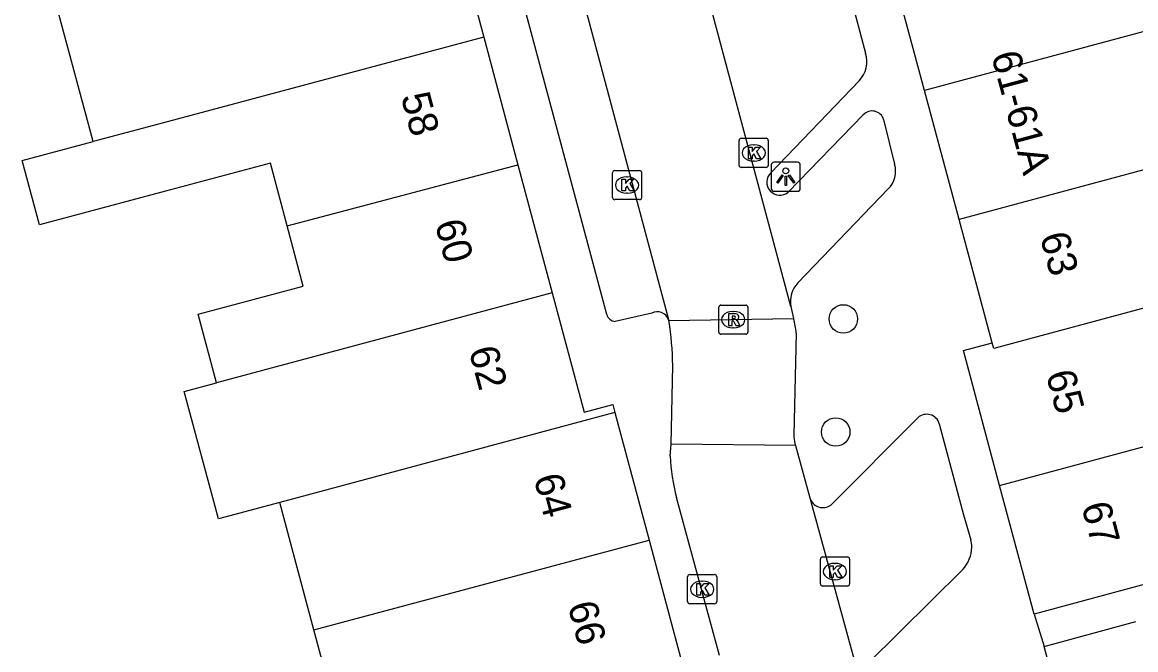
# Model space of a CAD drawing. Extents: x 162542 to 163144, y 380786 to 381511.
# Drawn here: x 162823.08 to 162861.28, y 380893 to 380914.51 of the extents above; entities that cross this region are included whole.
import ezdxf

# ---------------------------------------------------------------- set-up
doc = ezdxf.new("R2010")
doc.units = 0
for name, color, linetype in [('IMGEO_Boom', 7, 'Continuous'), ('IMGEO_Kolk', 7, 'Continuous'), ('IMGEO_Lichtpunt', 7, 'Continuous'), ('IMGEO_Pand', 7, 'Continuous'), ('IMGEO_Pand_nummerreeks', 7, 'Continuous'), ('IMGEO_Rijbaan_lokaal_open', 7, 'Continuous'), ('IMGEO_Rioolput', 7, 'Continuous'), ('IMGEO_Voetpad_open', 7, 'Continuous')]:
    doc.layers.add(name, color=color, linetype=linetype)

msp = doc.modelspace()

# ---------------------------------------------------------------- linework, layer by layer
at = {"layer": 'IMGEO_Boom'}
for centre in [(162851.249, 380904.339), (162850.989, 380900.462)]:
    msp.add_circle(centre, 0.489, dxfattribs=at)
at = {"layer": 'IMGEO_Kolk'}
for p, q in [((162847.674, 380909.606), (162847.674, 380910.458)), ((162847.749, 380910.532), (162848.601, 380910.532)), ((162848.162, 380910.312), (162848.187, 380910.312)), ((162848.675, 380910.458), (162848.675, 380909.606)), ((162848.185, 380909.752), (162848.16, 380909.752)), ((162843.329, 380908.503), (162843.329, 380909.355)), ((162843.404, 380909.429), (162844.256, 380909.429)), ((162843.817, 380909.209), (162843.842, 380909.209)), ((162844.33, 380909.355), (162844.33, 380908.503)), ((162848.601, 380909.532), (162847.749, 380909.532)), ((162844.256, 380908.429), (162843.404, 380908.429)), ((162843.84, 380908.649), (162843.815, 380908.649)), ((162850.536, 380896.179), (162851.388, 380896.179)), ((162850.461, 380895.253), (162850.461, 380896.105)), ((162850.949, 380895.959), (162850.974, 380895.959)), ((162851.462, 380896.105), (162851.462, 380895.253)), ((162845.906, 380894.646), (162845.906, 380895.498)), ((162845.981, 380895.572), (162846.833, 380895.572)), ((162846.907, 380895.498), (162846.907, 380894.646)), ((162846.394, 380895.352), (162846.419, 380895.352)), ((162851.388, 380895.179), (162850.536, 380895.179)), ((162850.972, 380895.399), (162850.947, 380895.399)), ((162846.417, 380894.792), (162846.392, 380894.792)), ((162846.833, 380894.572), (162845.981, 380894.572))]:
    msp.add_line(p, q, dxfattribs=at)
for points in [[(162847.674, 380909.606), (162847.674, 380910.458)], [(162847.749, 380910.532), (162848.601, 380910.532)], [(162848.675, 380910.458), (162848.675, 380909.606)], [(162847.995, 380910.232), (162848.118, 380910.232), (162848.118, 380910.081), (162848.248, 380910.232), (162848.412, 380910.232), (162848.266, 380910.081), (162848.419, 380909.832), (162848.267, 380909.832), (162848.182, 380909.996), (162848.118, 380909.929), (162848.118, 380909.832), (162847.995, 380909.832), (162847.995, 380910.232)], [(162843.329, 380908.503), (162843.329, 380909.355)], [(162843.404, 380909.429), (162844.256, 380909.429)], [(162844.33, 380909.355), (162844.33, 380908.503)], [(162848.601, 380909.532), (162847.749, 380909.532)], [(162843.65, 380909.129), (162843.773, 380909.129), (162843.773, 380908.978), (162843.903, 380909.129), (162844.067, 380909.129), (162843.921, 380908.978), (162844.074, 380908.729), (162843.922, 380908.729), (162843.837, 380908.893), (162843.773, 380908.826), (162843.773, 380908.729), (162843.65, 380908.729), (162843.65, 380909.129)], [(162844.256, 380908.429), (162843.404, 380908.429)], [(162850.536, 380896.179), (162851.388, 380896.179)], [(162850.461, 380895.253), (162850.461, 380896.105)], [(162850.782, 380895.879), (162850.905, 380895.879), (162850.905, 380895.728), (162851.035, 380895.879), (162851.199, 380895.879), (162851.053, 380895.728), (162851.206, 380895.479), (162851.054, 380895.479), (162850.969, 380895.643), (162850.905, 380895.576), (162850.905, 380895.479), (162850.782, 380895.479), (162850.782, 380895.879)], [(162851.462, 380896.105), (162851.462, 380895.253)], [(162845.906, 380894.646), (162845.906, 380895.498)], [(162845.981, 380895.572), (162846.833, 380895.572)], [(162846.907, 380895.498), (162846.907, 380894.646)], [(162846.227, 380895.272), (162846.35, 380895.272), (162846.35, 380895.121), (162846.48, 380895.272), (162846.644, 380895.272), (162846.498, 380895.121), (162846.651, 380894.872), (162846.499, 380894.872), (162846.414, 380895.036), (162846.35, 380894.969), (162846.35, 380894.872), (162846.227, 380894.872), (162846.227, 380895.272)], [(162851.388, 380895.179), (162850.536, 380895.179)], [(162846.833, 380894.572), (162845.981, 380894.572)]]:
    msp.add_lwpolyline(points, dxfattribs=at)
for centre, start, end in [((162847.751, 380910.456), 91.552, 178.448), ((162847.751, 380910.456), 91.552, 178.448), ((162848.599, 380910.456), 1.552, 88.448), ((162848.599, 380910.456), 1.552, 88.448), ((162847.751, 380909.608), 181.552, 268.448), ((162847.751, 380909.608), 181.552, 268.448), ((162848.599, 380909.608), 271.552, 358.448), ((162848.599, 380909.608), 271.552, 358.448), ((162843.406, 380909.353), 91.552, 178.448), ((162843.406, 380909.353), 91.552, 178.448), ((162844.254, 380909.353), 1.552, 88.448), ((162844.254, 380909.353), 1.552, 88.448), ((162843.406, 380908.505), 181.552, 268.448), ((162843.406, 380908.505), 181.552, 268.448), ((162844.254, 380908.505), 271.552, 358.448), ((162844.254, 380908.505), 271.552, 358.448), ((162850.538, 380896.103), 91.552, 178.448), ((162850.538, 380896.103), 91.552, 178.448), ((162851.386, 380896.103), 1.552, 88.448), ((162851.386, 380896.103), 1.552, 88.448), ((162845.983, 380895.496), 91.552, 178.448), ((162845.983, 380895.496), 91.552, 178.448), ((162846.831, 380895.496), 1.552, 88.448), ((162846.831, 380895.496), 1.552, 88.448), ((162850.538, 380895.255), 181.552, 268.448), ((162850.538, 380895.255), 181.552, 268.448), ((162851.386, 380895.255), 271.552, 358.448), ((162851.386, 380895.255), 271.552, 358.448), ((162845.983, 380894.648), 181.552, 268.448), ((162845.983, 380894.648), 181.552, 268.448), ((162846.831, 380894.648), 271.552, 358.448), ((162846.831, 380894.648), 271.552, 358.448)]:
    msp.add_arc(centre, 0.0765, start, end, dxfattribs=at)
for centre, major_axis, ratio, start_param, end_param in [((162848.161, 380910.032), (-0.387, 0.002), 0.722429, 4.712389, 7.853982), ((162848.186, 380910.032), (-0.39, 0.002), 0.717154, 1.570796, 4.712389), ((162843.816, 380908.929), (-0.387, 0.002), 0.722429, 4.712389, 7.853982), ((162843.841, 380908.929), (-0.39, 0.002), 0.717154, 1.570796, 4.712389), ((162850.948, 380895.679), (-0.387, 0.002), 0.722429, 4.712389, 7.853982), ((162850.973, 380895.679), (-0.39, 0.002), 0.717154, 1.570796, 4.712389), ((162846.393, 380895.072), (-0.387, 0.002), 0.722429, 4.712389, 7.853982), ((162846.418, 380895.072), (-0.39, 0.002), 0.717154, 1.570796, 4.712389)]:
    msp.add_ellipse(centre, major_axis=major_axis, ratio=ratio, start_param=start_param, end_param=end_param, dxfattribs=at)
at = {"layer": 'IMGEO_Lichtpunt'}
for p, q in [((162848.776, 380909.618), (162848.776, 380908.811)), ((162848.776, 380909.618), (162848.776, 380908.811)), ((162849.678, 380909.713), (162848.87, 380909.713)), ((162849.678, 380909.713), (162848.87, 380909.713)), ((162849.772, 380908.811), (162849.772, 380909.618)), ((162849.772, 380908.811), (162849.772, 380909.618)), ((162848.87, 380908.717), (162849.678, 380908.717)), ((162848.87, 380908.717), (162849.678, 380908.717))]:
    msp.add_line(p, q, dxfattribs=at)
for points in [[(162849.15, 380909.282), (162849.189, 380909.254), (162849.001, 380908.992), (162848.963, 380909.019), (162849.15, 380909.282)], [(162849.252, 380909.234), (162849.299, 380909.234), (162849.299, 380908.912), (162849.252, 380908.912), (162849.252, 380909.234)], [(162849.362, 380909.254), (162849.4, 380909.281), (162849.587, 380909.019), (162849.548, 380908.991), (162849.362, 380909.254)]]:
    msp.add_lwpolyline(points, dxfattribs=at)
msp.add_circle((162849.275, 380909.416), 0.0994, dxfattribs=at)
for centre, start, end in [((162848.87, 380909.618), 90, 180), ((162848.87, 380909.618), 90, 180), ((162849.678, 380909.618), 0, 90), ((162849.678, 380909.618), 0, 90), ((162848.87, 380908.811), 180, 270), ((162848.87, 380908.811), 180, 270), ((162849.678, 380908.811), 270, 0), ((162849.678, 380908.811), 270, 360)]:
    msp.add_arc(centre, 0.0946, start, end, dxfattribs=at)
at = {"layer": 'IMGEO_Pand'}
for points in [[(162837.741, 380918.379), (162838.912, 380914.003)], [(162854.034, 380912.167), (162852.845, 380916.589)], [(162825.505, 380910.42), (162824.335, 380914.784)], [(162862.161, 380914.352), (162854.034, 380912.167)], [(162838.912, 380914.003), (162827.404, 380910.928), (162825.505, 380910.42)], [(162838.912, 380914.003), (162840.083, 380909.627)], [(162855.223, 380907.745), (162854.034, 380912.167)], [(162866.707, 380910.832), (162855.223, 380907.745)], [(162832.165, 380907.529), (162831.59, 380909.682), (162827.994, 380908.721), (162823.668, 380907.565), (162823.078, 380909.771), (162825.505, 380910.42)], [(162832.165, 380907.529), (162840.083, 380909.627)], [(162840.083, 380909.627), (162841.258, 380905.238)], [(162856.358, 380903.525), (162855.223, 380907.745)], [(162829.742, 380902.151), (162829.113, 380904.502), (162832.717, 380905.466), (162832.165, 380907.529)], [(162841.258, 380905.238), (162829.742, 380902.151)], [(162841.258, 380905.238), (162842.355, 380901.14), (162843.341, 380901.403), (162843.414, 380901.131)], [(162863.302, 380905.175), (162856.414, 380903.323), (162856.358, 380903.525)], [(162856.611, 380898.634), (162855.367, 380903.258), (162856.358, 380903.525)], [(162831.918, 380898.048), (162829.81, 380897.482), (162828.637, 380901.855), (162829.742, 380902.151)], [(162856.611, 380898.634), (162868.063, 380901.714)], [(162843.414, 380901.131), (162836.687, 380899.327), (162835.449, 380898.995), (162834.559, 380898.756), (162831.918, 380898.048)], [(162843.414, 380901.131), (162844.582, 380896.759)], [(162857.799, 380894.216), (162856.611, 380898.634)], [(162833.086, 380893.676), (162832.421, 380896.165), (162831.918, 380898.048)], [(162869.251, 380897.297), (162865.74, 380896.352), (162862.628, 380895.515), (162857.799, 380894.216)], [(162833.086, 380893.676), (162844.582, 380896.759)], [(162844.582, 380896.759), (162845.752, 380892.384)], [(162834.249, 380889.327), (162833.628, 380891.65), (162833.086, 380893.676)]]:
    msp.add_lwpolyline(points, dxfattribs=at)
at = {"layer": 'IMGEO_Rijbaan_lokaal_open'}
for points in [[(162833.101, 380949.771), (162845.249, 380904.323)], [(162849.452, 380904.763), (162838.69, 380945.047)], [(162849.452, 380904.763), (162849.544, 380904.353)], [(162845.265, 380904.285), (162845.249, 380904.323)], [(162845.265, 380904.285), (162849.544, 380904.353)], [(162849.634, 380903.856), (162849.549, 380900.368)], [(162845.34, 380900.044), (162845.396, 380902.748)], [(162845.309, 380899.648), (162845.34, 380900.044)], [(162849.608, 380900.004), (162845.34, 380900.044)], [(162849.59, 380900.072), (162849.608, 380900.004)], [(162849.608, 380900.004), (162850.098, 380898.2)], [(162847.005, 380892.801), (162845.528, 380898.214)], [(162850.098, 380898.2), (162851.913, 380891.569)]]:
    msp.add_lwpolyline(points, dxfattribs=at)
for centre, radius, start, end in [((162834.894, 380902.627), 10.503, 0.6601, 9.0831), ((162845.949, 380903.445), 3.708, 6.3585, 14.17), ((162850.83, 380900.395), 1.282, 181.191, 194.5811), ((162852.255, 380899.975), 6.953, 182.6956, 194.6706)]:
    msp.add_arc(centre, radius, start, end, dxfattribs=at)
at = {"layer": 'IMGEO_Rioolput'}
for p, q in [((162846.973, 380903.889), (162846.973, 380904.741)), ((162847.048, 380904.815), (162847.9, 380904.815)), ((162847.461, 380904.595), (162847.486, 380904.595)), ((162847.974, 380904.741), (162847.974, 380903.889)), ((162847.9, 380903.815), (162847.048, 380903.815)), ((162847.484, 380904.035), (162847.459, 380904.035))]:
    msp.add_line(p, q, dxfattribs=at)
for points in [[(162846.973, 380903.889), (162846.973, 380904.741)], [(162847.048, 380904.815), (162847.9, 380904.815)], [(162847.974, 380904.741), (162847.974, 380903.889)], [(162847.562, 380904.513), (162847.31, 380904.515), (162847.31, 380904.115)], [(162847.31, 380904.115), (162847.434, 380904.115), (162847.434, 380904.277), (162847.445, 380904.277)], [(162847.488, 380904.434), (162847.434, 380904.434), (162847.434, 380904.353)], [(162847.434, 380904.353), (162847.486, 380904.353)], [(162847.492, 380904.248), (162847.563, 380904.115), (162847.703, 380904.115), (162847.638, 380904.241)], [(162847.9, 380903.815), (162847.048, 380903.815)]]:
    msp.add_lwpolyline(points, dxfattribs=at)
for centre, radius, start, end in [((162847.05, 380904.739), 0.0765, 91.552, 178.448), ((162847.05, 380904.739), 0.0765, 91.552, 178.448), ((162847.898, 380904.739), 0.0765, 1.552, 88.448), ((162847.898, 380904.739), 0.0765, 1.552, 88.448), ((162847.444, 380904.224), 0.0533, 26.0293, 88.6989), ((162847.47, 380904.542), 0.19, 274.7715, 282.9687), ((162847.494, 380904.338), 0.0964, 77.0061, 93.1865), ((162847.508, 380904.395), 0.0378, 276.6634, 79.6772), ((162847.561, 380904.403), 0.109, 350.3612, 89.416), ((162847.559, 380904.403), 0.112, 277.5842, 350.9817), ((162847.543, 380904.188), 0.108, 29.5134, 73.7905), ((162847.05, 380903.891), 0.0765, 181.552, 268.448), ((162847.05, 380903.891), 0.0765, 181.552, 268.448), ((162847.898, 380903.891), 0.0765, 271.552, 358.448), ((162847.898, 380903.891), 0.0765, 271.552, 358.448)]:
    msp.add_arc(centre, radius, start, end, dxfattribs=at)
for centre, major_axis, ratio, start_param, end_param in [((162847.46, 380904.315), (-0.387, 0.002), 0.722429, 4.712389, 7.853982), ((162847.485, 380904.315), (-0.39, 0.002), 0.717154, 1.570796, 4.712389)]:
    msp.add_ellipse(centre, major_axis=major_axis, ratio=ratio, start_param=start_param, end_param=end_param, dxfattribs=at)
at = {"layer": 'IMGEO_Voetpad_open'}
for points in [[(162843.131, 380904.495), (162831.307, 380948.599)], [(162846.658, 380933.566), (162852.015, 380913.45)], [(162851.793, 380912.507), (162848.757, 380909.349)], [(162849.355, 380908.684), (162851.934, 380911.339)], [(162852.631, 380911.18), (162853.009, 380909.647)], [(162852.789, 380908.797), (162849.683, 380905.576)], [(162844.684, 380904.537), (162843.42, 380904.252)], [(162850.822, 380897.957), (162853.809, 380900.954)], [(162854.543, 380900.746), (162855.369, 380897.623), (162855.622, 380896.764)], [(162855.346, 380895.748), (162852.093, 380892.531)], [(162857.799, 380894.216), (162858.143, 380893.113)], [(162858.143, 380893.113), (162861.291, 380893.96)], [(162859.959, 380886.034), (162858.921, 380890.221), (162858.143, 380893.113)]]:
    msp.add_lwpolyline(points, dxfattribs=at)
for centre, radius, start, end in [((162851.122, 380913.163), 0.938, 315.6745, 17.831), ((162852.236, 380911.056), 0.414, 17.3703, 136.9288), ((162852.205, 380909.401), 0.84, 313.9883, 16.9896), ((162849.071, 380909.03), 0.448, 134.5742, 309.3526), ((162850.392, 380904.935), 0.955, 137.8812, 190.3956), ((162844.872, 380904.182), 0.402, 20.5702, 117.9403), ((162843.458, 380904.59), 0.34, 196.224, 263.6597), ((162854.111, 380900.621), 0.45, 16.1305, 132.2263), ((162850.548, 380898.34), 0.471, 197.2684, 305.6245), ((162854.527, 380896.47), 1.134, 2.2411, 15.0445), ((162854.481, 380896.55), 1.179, 317.1621, 358.2583)]:
    msp.add_arc(centre, radius, start, end, dxfattribs=at)

# ---------------------------------------------------------------- texts
at = {"layer": 'IMGEO_Pand_nummerreeks'}
for s, rotation, p in [('61-61A', 285.0514, (162856.316, 380913.385)), ('58', 284.9826, (162836.062, 380911.969)), ('60', 284.9835, (162837.226, 380907.616)), ('63', 285.0514, (162857.986, 380907.178)), ('62', 284.9826, (162838.39, 380903.27)), ('65', 285.0571, (162858.193, 380902.45)), ('64', 284.9654, (162840.617, 380898.895)), ('67', 285.0544, (162859.409, 380897.929)), ('66', 284.9654, (162841.786, 380894.522))]:
    msp.add_text(s, height=1, rotation=rotation, dxfattribs=at).set_placement(p)

doc.saveas('drawing.dxf')
